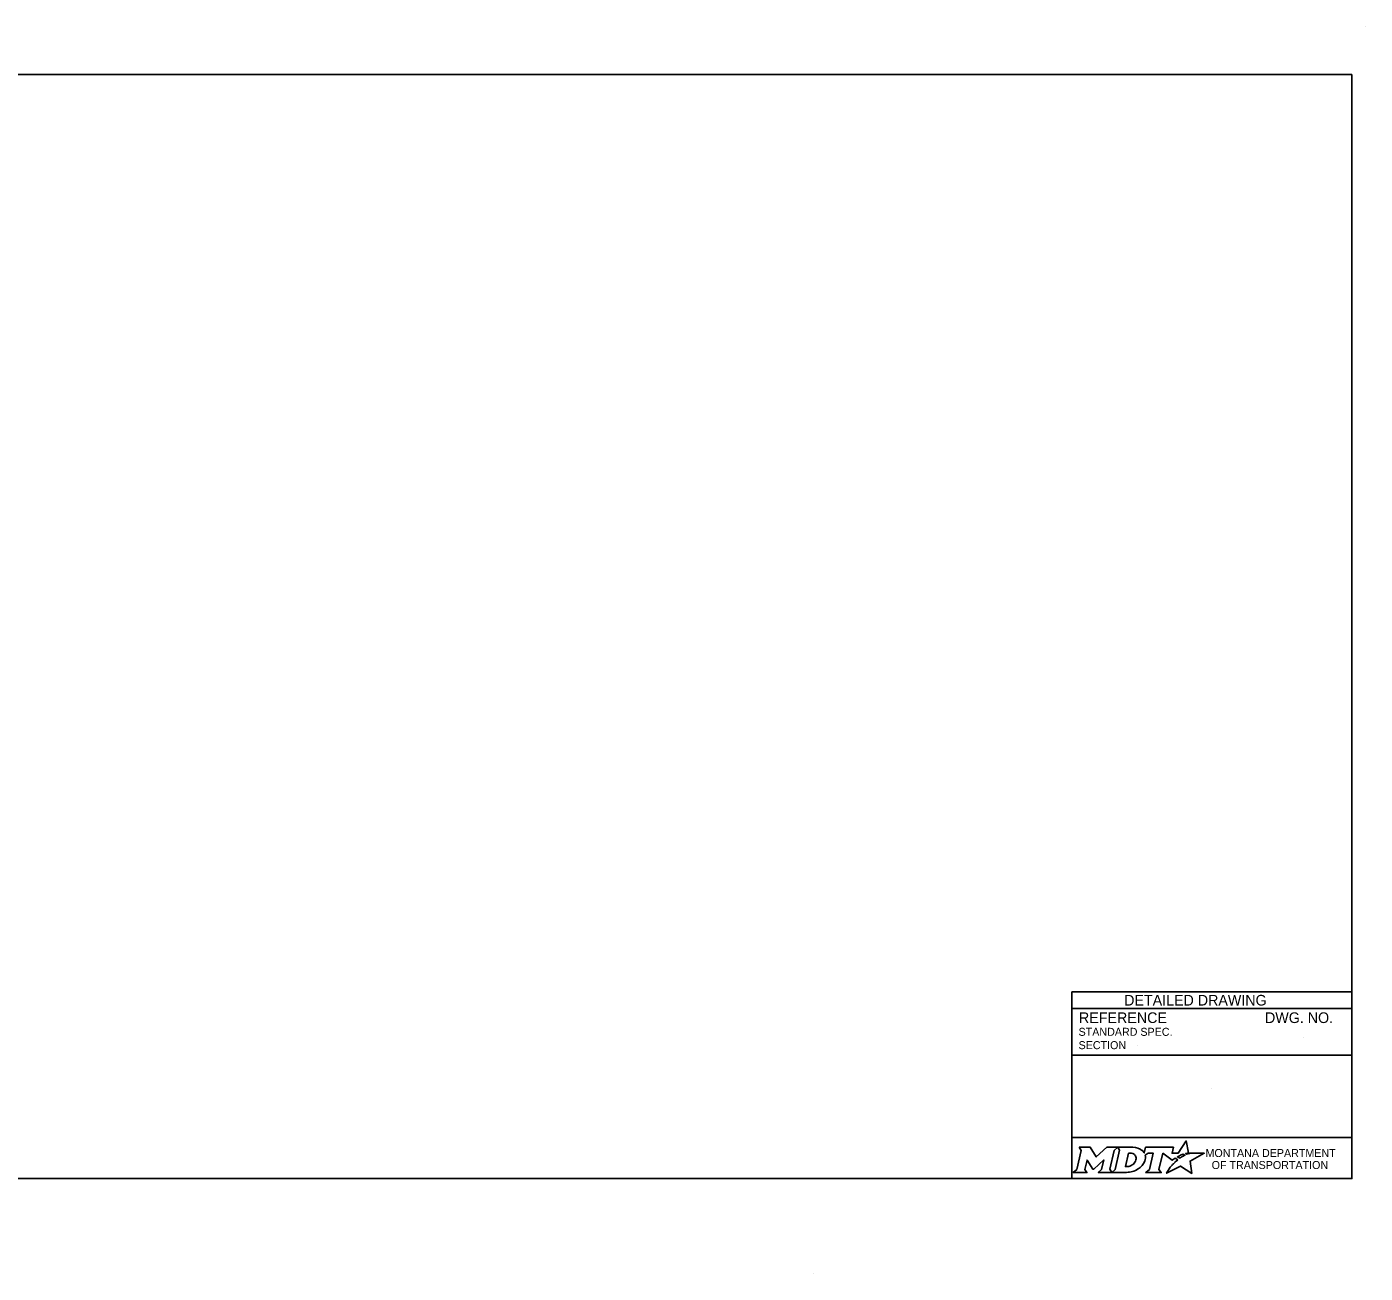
# Model space of a CAD drawing. Extents: x 49991 to 50160, y 49948 to 50051.
# Drawn here: x 50011 to 50021.04, y 49999.18 to 50008.52 of the extents above; entities that cross this region are included whole.
import ezdxf

# ---------------------------------------------------------------- set-up
doc = ezdxf.new("R2010")
doc.units = 0
for name, color, linetype in [('Default', 7, 'Continuous'), ('Level 1', 7, 'Continuous'), ('Level 4', 7, 'Continuous')]:
    doc.layers.add(name, color=color, linetype=linetype)

msp = doc.modelspace()

# ---------------------------------------------------------------- linework, layer by layer
at = {"layer": 'Default'}
for points in [[(50018.893, 50000.121), (50018.907, 50000.097), (50018.874, 49999.954), (50018.848, 49999.931), (50018.95, 49999.931), (50018.936, 49999.954), (50018.952, 50000.024), (50018.996, 49999.955), (50019.002, 49999.955), (50019.077, 50000.025), (50019.06, 49999.954), (50019.035, 49999.932), (50019.137, 49999.932), (50019.123, 49999.955), (50019.156, 50000.097)], [(50019.156, 50000.097), (50019.182, 50000.121), (50019.099, 50000.121), (50019.02, 50000.048), (50018.975, 50000.12), (50018.893, 50000.121)], [(50019.295, 50000.121), (50019.182, 50000.121), (50019.196, 50000.098), (50019.163, 49999.954), (50019.137, 49999.932), (50019.248, 49999.932)], [(50019.7, 50000.068), (50019.69, 50000.074), (50019.702, 50000.076), (50019.713, 50000.078), (50019.696, 50000.168), (50019.636, 50000.077), (50019.589, 50000.076), (50019.599, 50000.12), (50019.39, 50000.121), (50019.38, 50000.078), (50019.374, 50000.086)], [(50019.319, 50000.034), (50019.318, 50000.026), (50019.315, 50000.017), (50019.311, 50000.008), (50019.305, 50000.001), (50019.299, 49999.994), (50019.291, 49999.988), (50019.282, 49999.983), (50019.273, 49999.979), (50019.264, 49999.977), (50019.255, 49999.976), (50019.239, 49999.976), (50019.263, 50000.076), (50019.279, 50000.076), (50019.286, 50000.075), (50019.294, 50000.073), (50019.301, 50000.07), (50019.307, 50000.066), (50019.311, 50000.061), (50019.315, 50000.055), (50019.318, 50000.049), (50019.319, 50000.042), (50019.32, 50000.038), (50019.319, 50000.034)], [(50019.387, 50000.062), (50019.411, 50000.075), (50019.448, 50000.075), (50019.42, 49999.954), (50019.392, 49999.931), (50019.508, 49999.931), (50019.491, 49999.954), (50019.52, 50000.075), (50019.591, 50000.023), (50019.612, 50000.038), (50019.632, 50000.027)], [(50019.576, 49999.971), (50019.561, 49999.947), (50019.556, 49999.939), (50019.55, 49999.931), (50019.548, 49999.926), (50019.653, 49999.979), (50019.737, 49999.924), (50019.724, 50000.017), (50019.831, 50000.075), (50019.782, 50000.076), (50019.751, 50000.077), (50019.731, 50000.077), (50019.724, 50000.075), (50019.719, 50000.074), (50019.711, 50000.072), (50019.7, 50000.068)], [(50019.65, 50000.04), (50019.648, 50000.039), (50019.629, 50000.048), (50019.639, 50000.054), (50019.644, 50000.056), (50019.652, 50000.06), (50019.658, 50000.063), (50019.666, 50000.066), (50019.673, 50000.068), (50019.685, 50000.061), (50019.681, 50000.059), (50019.676, 50000.056), (50019.672, 50000.054), (50019.667, 50000.051), (50019.665, 50000.05), (50019.662, 50000.049), (50019.66, 50000.047), (50019.658, 50000.046), (50019.655, 50000.044), (50019.652, 50000.042), (50019.65, 50000.04)], [(50019.293, 49999.939), (50019.302, 49999.942), (50019.315, 49999.947), (50019.335, 49999.958)], [(50019.59, 49999.987), (50019.59, 49999.987)]]:
    msp.add_lwpolyline(points, dxfattribs=at)
for centre, radius, start, end in [((50019.319, 50000.042), 0.0709, 339.5329, 15.8582), ((50019.274, 50000.059), 0.118, 300.9103, 339.1383)]:
    msp.add_arc(centre, radius, start, end, dxfattribs=at)
for centre, major_axis, ratio, start_param, end_param in [((50019.293, 50000.073), (0.0834, -0.0037), 0.568097, 0.61298, 1.570796), ((50019.349, 50000.081), (0.0361, -0.0295), 0.469099, 1.225588, 1.570796), ((50019.621, 50000.017), (-0.0112, -0.0097), 0.021651, 3.157348, 6.283185), ((50019.248, 50000.08), (0, 0.148), 0.987302, 3.139398, 3.456847), ((50019.583, 49999.979), (-0.00694, -0.00806), 0.008222, 0, 3.137361), ((50019.6, 49999.997), (-0.0098, -0.0102), 0.016458, 3.141593, 6.279097)]:
    msp.add_ellipse(centre, major_axis=major_axis, ratio=ratio, start_param=start_param, end_param=end_param, dxfattribs=at)
at = {"layer": 'Level 1'}
for p, q in [((50021.038, 50008.524), (50021.038, 50008.524)), ((50016.9, 49999.176), (50016.9, 49999.176))]:
    msp.add_line(p, q, dxfattribs=at)
msp.add_lwpolyline([(50020.938, 50008.165), (50009.737, 50008.165), (50009.737, 49999.886), (50020.938, 49999.886)], close=True, dxfattribs=at)
at = {"layer": 'Level 4'}
for p, q in [((50020.938, 50001.286), (50018.838, 50001.286)), ((50018.838, 50001.286), (50018.838, 49999.886)), ((50020.938, 50001.161), (50018.838, 50001.161)), ((50020.574, 50000.946), (50020.574, 50000.946)), ((50019.332, 50000.886), (50019.332, 50000.886)), ((50020.938, 50000.811), (50018.838, 50000.811)), ((50019.888, 50000.562), (50019.888, 50000.562)), ((50020.938, 50000.193), (50018.838, 50000.193))]:
    msp.add_line(p, q, dxfattribs=at)

# ---------------------------------------------------------------- texts
at = {"layer": 'Default'}
for s, p in [('MONTANA DEPARTMENT', (50019.84, 50000.047)), ('OF TRANSPORTATION', (50019.886, 49999.957))]:
    msp.add_text(s, height=0.06, rotation=360, dxfattribs=at).set_placement(p)
at = {"layer": 'Level 4'}
for s, height, p in [('DETAILED DRAWING', 0.0799, (50019.23, 50001.183)), ('REFERENCE', 0.08, (50018.891, 50001.052)), ('DWG. NO.', 0.08, (50020.286, 50001.052)), ('STANDARD SPEC.', 0.06, (50018.888, 50000.956)), ('SECTION', 0.06, (50018.888, 50000.856))]:
    msp.add_text(s, height=height, dxfattribs=at).set_placement(p)

doc.saveas('drawing.dxf')
